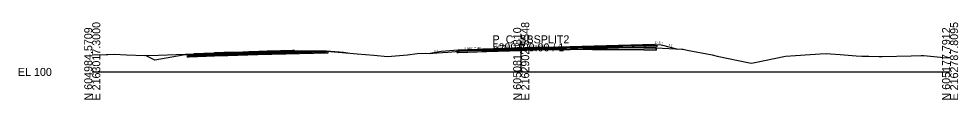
# Model space of a CAD drawing. Extents: x -26 to 1303, y -10 to 12033.
# Drawn here: x -25.7 to 302.8, y 9990.3 to 10017.3 of the extents above; entities that cross this region are included whole.
import ezdxf

# ---------------------------------------------------------------- set-up
doc = ezdxf.new("R2010")
doc.units = 0
for name, color, linetype in [('RD_GPK_XS_Cell', 7, 'Continuous'), ('RD_XS_Base', 7, 'Continuous'), ('RD_XS_ExGround', 7, 'Continuous'), ('RD_XS_ExPaveRet', 7, 'Continuous'), ('RD_XS_Greenside', 7, 'Continuous'), ('RD_XS_Pave', 7, 'Continuous'), ('RD_XS_PaveOvlay_CP', 7, 'Continuous'), ('RD_XS_TieSlope', 7, 'Continuous'), ('RD_XS_TX_Elev_EX', 7, 'Continuous'), ('RD_XS_TX_Elev_PR', 7, 'Continuous'), ('RD_XS_TX_ShdSlope', 7, 'Continuous'), ('RD_XS_TX_Slope', 7, 'Continuous')]:
    doc.layers.add(name, color=color, linetype=linetype)

msp = doc.modelspace()

# ---------------------------------------------------------------- linework, layer by layer
at = {"layer": 'RD_GPK_XS_Cell'}
for p, q in [((150, 10000), (150, 10010)), ((0, 10000), (150, 10000)), ((150, 10000), (300, 10000))]:
    msp.add_line(p, q, dxfattribs=at)
at = {"layer": 'RD_XS_Base'}
for p, q in [((128, 10007.26), (127.5, 10007.24)), ((127.5, 10007.24), (127.5, 10007.24)), ((127.5, 10007.24), (127.5, 10006.74)), ((138, 10007.66), (128, 10007.26)), ((128, 10007.26), (128, 10007.26)), ((128, 10006.76), (138, 10007.16)), ((136, 10007.58), (136, 10007.58)), ((150, 10008), (138, 10007.66)), ((138, 10007.16), (150, 10007.5)), ((150, 10008), (196.91, 10009.31)), ((197.41, 10008.82), (150, 10007.5)), ((150, 10007.5), (150, 10008.16)), ((150, 10008.16), (150, 10008.16)), ((150, 10008.16), (150, 10008.16)), ((150, 10008.16), (150, 10008)), ((150, 10008), (150, 10008)), ((150, 10007.5), (150, 10008)), ((150, 10008), (150, 10008)), ((150, 10008), (150, 10008)), ((150, 10007.5), (150, 10007.5)), ((162, 10008.33), (162, 10008.33)), ((162, 10008.33), (162, 10008.33)), ((162, 10007.83), (162, 10007.83)), ((162, 10007.83), (162, 10007.83)), ((196.91, 10009.31), (196.91, 10009.31)), ((197.41, 10009.32), (197.41, 10008.82)), ((197.41, 10009.29), (197.41, 10009.29)), ((33.35, 10005.64), (33.84, 10005.66)), ((33.35, 10005.63), (33.35, 10005.64)), ((33.35, 10005.14), (33.35, 10005.63)), ((33.84, 10005.16), (33.35, 10005.14)), ((33.84, 10005.66), (33.85, 10005.66)), ((33.85, 10005.16), (33.84, 10005.16)), ((33.85, 10005.66), (45.82, 10006.14)), ((45.82, 10005.64), (33.85, 10005.16)), ((45.82, 10006.14), (45.85, 10006.14)), ((45.85, 10005.64), (45.82, 10005.64)), ((45.85, 10006.14), (47.44, 10006.18)), ((47.44, 10005.68), (45.85, 10005.64)), ((47.44, 10006.18), (57.85, 10006.46)), ((57.85, 10005.96), (47.44, 10005.68)), ((57.85, 10006.46), (82.35, 10007.09)), ((57.85, 10005.96), (57.85, 10006.61)), ((57.85, 10006.61), (57.85, 10006.61)), ((57.85, 10006.61), (57.85, 10006.61)), ((57.85, 10006.61), (57.85, 10006.46)), ((82.35, 10006.59), (57.85, 10005.96)), ((57.85, 10006.46), (57.85, 10006.46)), ((57.85, 10005.96), (57.85, 10006.46)), ((57.85, 10006.46), (57.85, 10006.46)), ((57.85, 10006.46), (57.85, 10006.46)), ((57.85, 10005.96), (57.85, 10005.96)), ((81.85, 10007.08), (81.85, 10007.08)), ((81.85, 10007.08), (81.85, 10007.08)), ((81.85, 10007.08), (81.85, 10007.08)), ((81.85, 10006.58), (81.85, 10006.58)), ((81.85, 10006.58), (81.85, 10006.58)), ((82.35, 10007.09), (82.35, 10006.59)), ((82.35, 10007.06), (82.35, 10007.06)), ((127.5, 10006.74), (128, 10006.76)), ((128, 10006.76), (128, 10006.76)), ((136, 10007.08), (136, 10007.08))]:
    msp.add_line(p, q, dxfattribs=at)
at = {"layer": 'RD_XS_ExGround'}
msp.add_lwpolyline([(0, 10006), (4.81, 10006.09), (5.45, 10006.1), (7.69, 10006.19), (11.94, 10006.03), (18.4, 10005.76), (23.11, 10005.92), (35.53, 10006.35), (42.63, 10006.63), (46.01, 10006.74), (52.68, 10006.97), (54.7, 10007.03), (55.34, 10007.07), (61.62, 10007.23), (70.68, 10007.46), (78.62, 10007.42), (81.4, 10007.31), (82.01, 10007.26), (91.39, 10006.5), (92.61, 10006.38), (98.45, 10005.83), (103.23, 10005.38), (110.25, 10005.97), (113.67, 10006.5), (116.51, 10006.53), (117.97, 10006.45), (120.6, 10006.63), (124.38, 10006.9), (136.52, 10007.96), (147.95, 10008.29), (151.27, 10008.4), (152.14, 10008.44), (154.95, 10008.5), (155.35, 10008.51), (159.12, 10008.56), (167.16, 10008.65), (170.8, 10008.68), (174.92, 10008.63), (184.06, 10008.55), (192.89, 10008.45), (197.25, 10008.39), (206.2, 10007.93), (206.67, 10007.91), (208, 10007.64), (216.81, 10005.95), (218.51, 10005.5), (229.89, 10003.15), (230.52, 10003.02), (231.66, 10003.27), (242.44, 10005.49), (254.57, 10006.38), (256.62, 10006.49), (258.17, 10006.36), (261.6, 10006.09), (267.19, 10005.62), (269.14, 10005.51), (271.59, 10005.56), (275.2, 10005.38), (275.69, 10005.38), (276.26, 10005.37), (286.37, 10005.64), (289.93, 10005.74), (290.86, 10005.71), (296.69, 10005.13), (297.28, 10005.07), (300, 10004.97)], dxfattribs=at)
at = {"layer": 'RD_XS_ExPaveRet'}
for points in [[(70.68, 10007.46), (70.04, 10007.44), (61.62, 10007.23), (61.14, 10007.21), (55.34, 10007.07), (54.73, 10007.03), (54.7, 10007.03), (52.74, 10006.97), (52.68, 10006.97), (47.44, 10006.79), (46.01, 10006.74), (46.01, 10006.74), (42.63, 10006.63), (42.51, 10006.62), (35.53, 10006.35), (35.53, 10006.33), (35.53, 10005.6), (42.51, 10005.87), (42.63, 10005.88), (46.01, 10005.99), (46.01, 10005.99), (47.44, 10006.04), (52.68, 10006.22), (52.74, 10006.22), (54.7, 10006.28), (54.73, 10006.28), (55.34, 10006.32), (61.14, 10006.46), (61.62, 10006.48), (70.04, 10006.69), (70.68, 10006.71), (70.68, 10006.71), (70.68, 10006.71), (70.68, 10006.78), (70.68, 10007.46), (70.68, 10007.46), (70.68, 10007.46)], [(70.68, 10007.46), (70.04, 10007.44), (61.62, 10007.23), (61.14, 10007.21), (55.34, 10007.07), (54.73, 10007.03), (54.7, 10007.03), (52.74, 10006.97), (52.68, 10006.97), (47.44, 10006.79), (46.01, 10006.74), (46.01, 10006.74), (42.63, 10006.63), (42.51, 10006.62), (35.53, 10006.35), (35.53, 10006.33), (35.53, 10005.6), (42.51, 10005.87), (42.63, 10005.88), (46.01, 10005.99), (46.01, 10005.99), (47.44, 10006.04), (52.68, 10006.22), (52.74, 10006.22), (54.7, 10006.28), (54.73, 10006.28), (55.34, 10006.32), (61.14, 10006.46), (61.62, 10006.48), (70.04, 10006.69), (70.68, 10006.71), (70.68, 10006.71), (70.68, 10006.78), (70.68, 10007.46), (70.68, 10007.46)], [(197.25, 10008.39), (197.25, 10008.39), (197.25, 10007.64), (192.89, 10007.7), (192.89, 10007.7), (184.06, 10007.8), (184.06, 10007.8), (184.06, 10007.8), (174.92, 10007.88), (174.92, 10007.88), (170.8, 10007.93), (167.16, 10007.9), (167.16, 10007.9), (159.12, 10007.81), (159.12, 10007.81), (159.12, 10007.81), (155.35, 10007.76), (155.35, 10007.76), (154.95, 10007.75), (152.14, 10007.69), (152.14, 10007.69), (151.27, 10007.65), (151.27, 10007.65), (147.95, 10007.54), (147.95, 10007.54), (147.95, 10007.54), (136.52, 10007.21), (136.52, 10007.96), (136.52, 10007.96), (147.95, 10008.29), (147.95, 10008.29), (147.95, 10008.29), (151.27, 10008.4), (151.27, 10008.4), (152.14, 10008.44), (152.14, 10008.44), (154.95, 10008.5), (155.35, 10008.51), (155.35, 10008.51), (159.12, 10008.56), (159.12, 10008.56), (159.12, 10008.56), (167.16, 10008.65), (167.16, 10008.65), (170.8, 10008.68), (174.92, 10008.63), (174.92, 10008.63), (184.06, 10008.55), (184.06, 10008.55), (184.06, 10008.55), (192.89, 10008.45), (192.89, 10008.45), (197.25, 10008.39)], [(192.89, 10008.45), (184.06, 10008.55), (174.92, 10008.63), (170.8, 10008.68), (167.16, 10008.65), (159.12, 10008.56), (155.35, 10008.51), (154.95, 10008.5), (152.14, 10008.44), (151.27, 10008.4), (147.95, 10008.29), (136.52, 10007.96), (136.52, 10007.21), (147.95, 10007.54), (151.27, 10007.65), (152.14, 10007.69), (154.95, 10007.75), (155.35, 10007.76), (159.12, 10007.81), (167.16, 10007.9), (170.8, 10007.93), (174.92, 10007.88), (184.06, 10007.8), (192.89, 10007.7), (197.25, 10007.64), (197.25, 10008.39), (192.89, 10008.45)]]:
    msp.add_lwpolyline(points, dxfattribs=at)
at = {"layer": 'RD_XS_Greenside'}
for p, q in [((198.91, 10009.47), (204.75, 10008.01)), ((21.85, 10004.16), (18.62, 10005.77)), ((31.85, 10005.82), (21.85, 10004.16)), ((87.85, 10006.92), (89.37, 10006.66)), ((122, 10007.1), (118.17, 10006.46))]:
    msp.add_line(p, q, dxfattribs=at)
at = {"layer": 'RD_XS_Pave'}
for p, q in [((81.85, 10007.4), (57.85, 10006.77)), ((81.85, 10007.24), (57.85, 10006.61)), ((57.85, 10006.61), (81.85, 10007.24)), ((81.85, 10007.24), (81.85, 10007.4)), ((81.85, 10007.4), (81.85, 10007.4)), ((81.85, 10007.4), (81.85, 10007.4)), ((81.85, 10007.4), (81.85, 10007.4)), ((81.85, 10007.08), (81.85, 10007.24)), ((81.85, 10007.24), (81.85, 10007.24)), ((81.85, 10007.24), (81.85, 10007.24)), ((81.85, 10007.24), (81.85, 10007.24)), ((81.85, 10007.24), (81.85, 10007.24)), ((81.85, 10007.24), (81.85, 10007.24)), ((138, 10007.98), (128, 10007.58)), ((128, 10007.42), (138, 10007.82)), ((138, 10007.82), (128, 10007.42)), ((128, 10007.26), (138, 10007.66)), ((128, 10007.58), (128, 10007.58)), ((128, 10007.58), (128, 10007.42)), ((128, 10007.42), (128, 10007.42)), ((128, 10007.42), (128, 10007.26)), ((136, 10007.9), (136, 10007.9)), ((136, 10007.74), (136, 10007.74)), ((136, 10007.74), (136, 10007.74)), ((136, 10007.58), (136, 10007.58)), ((150, 10008.31), (138, 10007.98)), ((138, 10007.82), (150, 10008.16)), ((150, 10008.16), (138, 10007.82)), ((138, 10007.66), (150, 10008)), ((196.91, 10009.63), (150, 10008.31)), ((196.91, 10009.47), (150, 10008.16)), ((150, 10008.16), (196.91, 10009.47)), ((150, 10008), (197.41, 10009.32)), ((150, 10008.31), (150, 10008.31)), ((150, 10008.16), (150, 10008.16)), ((150, 10008.16), (150, 10008.16)), ((150, 10008.16), (150, 10008)), ((150, 10008.16), (150, 10008.16)), ((150, 10008), (150, 10008.16)), ((150, 10008.16), (150, 10008.16)), ((150, 10008.16), (150, 10008.16)), ((150, 10008), (150, 10008)), ((150, 10008), (150, 10008)), ((162, 10008.65), (162, 10008.65)), ((162, 10008.65), (162, 10008.65)), ((162, 10008.49), (162, 10008.49)), ((162, 10008.49), (162, 10008.49)), ((162, 10008.49), (162, 10008.49)), ((162, 10008.49), (162, 10008.49)), ((162, 10008.33), (162, 10008.33)), ((162, 10008.33), (162, 10008.33)), ((196.91, 10009.47), (196.91, 10009.63)), ((196.91, 10009.63), (196.91, 10009.63)), ((196.91, 10009.31), (196.91, 10009.47)), ((196.91, 10009.47), (196.91, 10009.47)), ((33.85, 10005.98), (45.82, 10006.46)), ((45.82, 10006.3), (33.85, 10005.82)), ((33.85, 10005.82), (45.82, 10006.3)), ((45.82, 10006.14), (33.85, 10005.66)), ((33.85, 10005.82), (33.85, 10005.98)), ((33.85, 10005.98), (33.85, 10005.98)), ((33.85, 10005.66), (33.85, 10005.82)), ((33.85, 10005.82), (33.85, 10005.82)), ((45.82, 10006.46), (45.85, 10006.46)), ((45.85, 10006.3), (45.82, 10006.3)), ((45.82, 10006.3), (45.85, 10006.3)), ((45.85, 10006.14), (45.82, 10006.14)), ((45.85, 10006.46), (47.44, 10006.5)), ((47.44, 10006.34), (45.85, 10006.3)), ((45.85, 10006.3), (47.44, 10006.34)), ((47.44, 10006.18), (45.85, 10006.14)), ((47.44, 10006.5), (57.85, 10006.77)), ((57.85, 10006.61), (47.44, 10006.34)), ((47.44, 10006.34), (57.85, 10006.61)), ((57.85, 10006.46), (47.44, 10006.18)), ((57.85, 10006.46), (81.85, 10007.08)), ((57.85, 10006.77), (57.85, 10006.77)), ((57.85, 10006.61), (57.85, 10006.61)), ((57.85, 10006.61), (57.85, 10006.61)), ((57.85, 10006.61), (57.85, 10006.46)), ((57.85, 10006.61), (57.85, 10006.61)), ((57.85, 10006.46), (57.85, 10006.61)), ((57.85, 10006.61), (57.85, 10006.61)), ((57.85, 10006.61), (57.85, 10006.61)), ((57.85, 10006.46), (57.85, 10006.46)), ((57.85, 10006.46), (57.85, 10006.46)), ((81.85, 10007.08), (81.85, 10007.08)), ((81.85, 10007.08), (81.85, 10007.08))]:
    msp.add_line(p, q, dxfattribs=at)
at = {"layer": 'RD_XS_PaveOvlay_CP'}
for p, q in [((81.85, 10007.4), (57.85, 10006.77)), ((81.85, 10007.4), (81.85, 10007.4)), ((81.85, 10007.4), (81.85, 10007.4)), ((138, 10007.98), (128, 10007.58)), ((136, 10007.9), (136, 10007.9)), ((150, 10008.31), (138, 10007.98)), ((162, 10008.65), (150, 10008.31)), ((150, 10008.31), (150, 10008.31)), ((162, 10008.65), (162, 10008.65)), ((162, 10008.65), (162, 10008.65)), ((33.85, 10005.98), (45.82, 10006.46)), ((45.82, 10006.46), (45.85, 10006.46)), ((45.85, 10006.46), (47.44, 10006.5)), ((47.44, 10006.5), (57.85, 10006.77)), ((57.85, 10006.77), (57.85, 10006.77))]:
    msp.add_line(p, q, dxfattribs=at)
at = {"layer": 'RD_XS_TieSlope'}
for p, q in [((81.85, 10007.4), (87.85, 10006.92)), ((128, 10007.58), (122, 10007.1)), ((196.91, 10009.63), (198.91, 10009.47)), ((33.85, 10005.98), (31.85, 10005.82))]:
    msp.add_line(p, q, dxfattribs=at)

# ---------------------------------------------------------------- texts
at = {"layer": 'RD_GPK_XS_Cell'}
for s, p in [('E 2163017.3000', (2.8, 9990)), ('E 2162902.5548', (152.8, 9990)), ('E 2162787.8095', (302.8, 9990)), ('N 604984.5709', (0, 9990)), ('N 605081.1810', (150, 9990)), ('N 605177.7912', (300, 9990))]:
    msp.add_text(s, height=2.8, rotation=90, dxfattribs=at).set_placement(p)
for s, p in [('P_C_SBSPLIT2', (140, 10010)), ('5299+00.00 / 1', (140, 10007.2)), ('EL 100', (-26, 9998.6))]:
    msp.add_text(s, height=2.8, dxfattribs=at).set_placement(p)
at = {"layer": 'RD_XS_TX_Elev_EX'}
msp.add_text('108.36', height=0.6, rotation=90, dxfattribs=at).set_placement((149.71, 10009.28))
at = {"layer": 'RD_XS_TX_Elev_PR'}
msp.add_text('108.31', height=1, rotation=90, dxfattribs=at).set_placement((151.28, 10008.78))
at = {"layer": 'RD_XS_TX_ShdSlope'}
msp.add_text('12.5:1', height=0.75, rotation=355.4261, dxfattribs=at).set_placement((196.64, 10009.94))
at = {"layer": 'RD_XS_TX_Slope'}
for s, rotation, p in [('6:1', 9.4623, (119.74, 10006.84)), ('0.040 FT./FT.', 2.2906, (130.15, 10007.78)), ('0.030 FT./FT.', 1.7184, (140.33, 10008.37)), ('0.030 FT./FT.', 1.7184, (153.16, 10008.58)), ('4:1', 350.5358, (201.5, 10009.14))]:
    msp.add_text(s, height=0.75, rotation=rotation, dxfattribs=at).set_placement(p)

doc.saveas('drawing.dxf')
